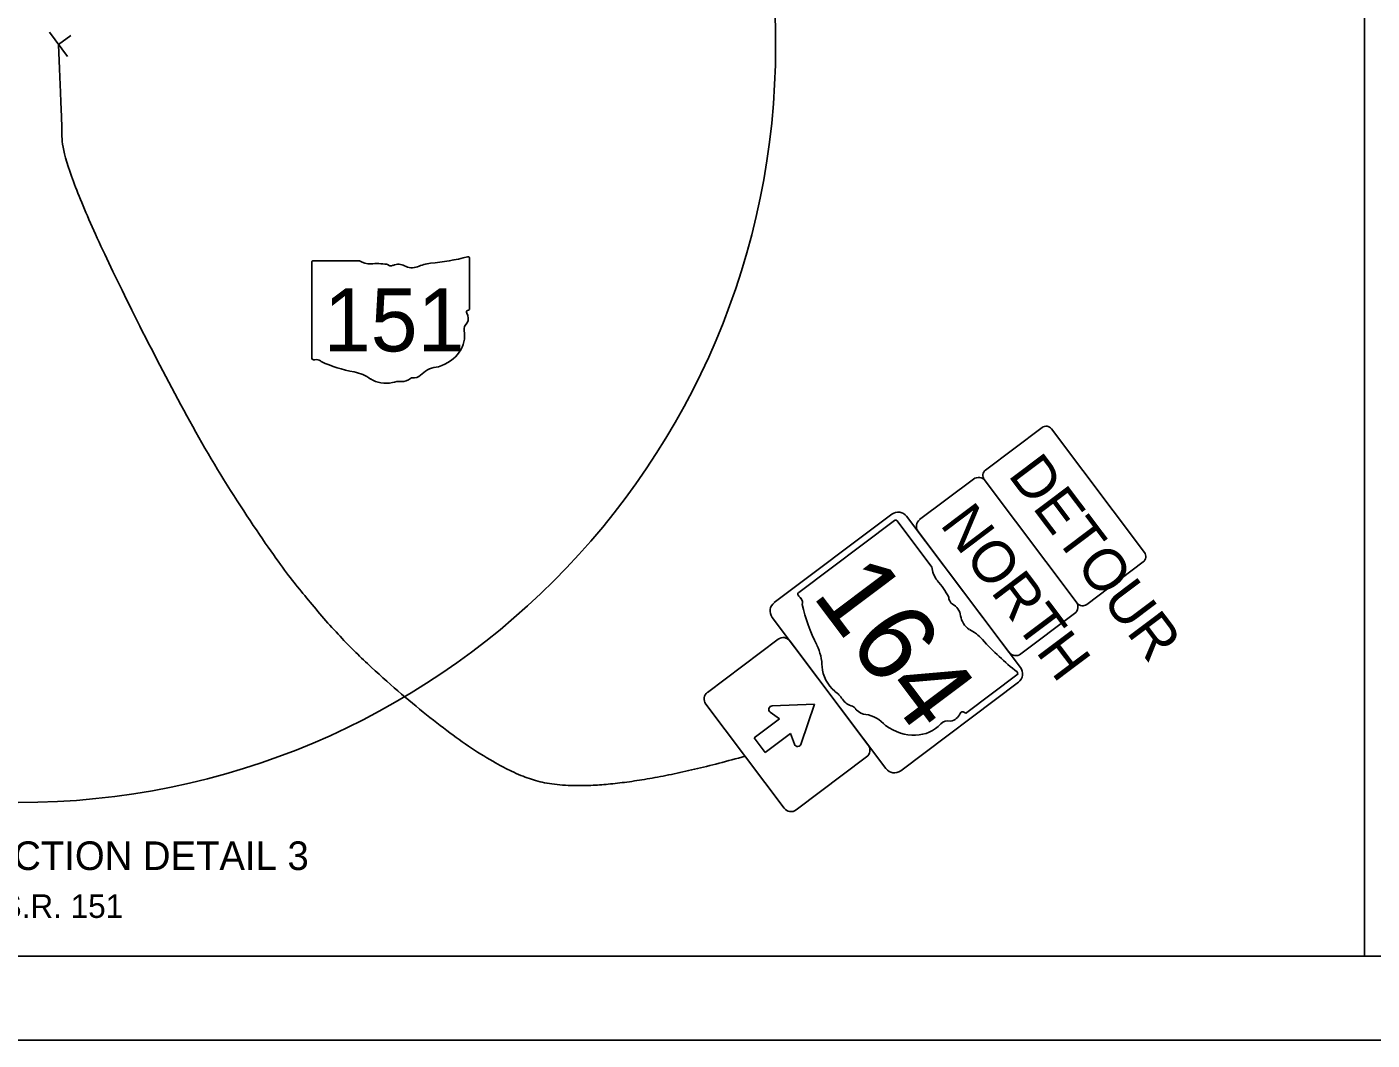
# Model space of a CAD drawing. Extents: x -740 to 1519, y 0 to 440.
# Drawn here: x 191 to 350.9, y 0 to 120.5 of the extents above; entities that cross this region are included whole.
import ezdxf

# ---------------------------------------------------------------- set-up
doc = ezdxf.new("R2010")
doc.units = 0
for name, color, linetype in [('GM_X_County_Road_Text', 7, 'Continuous'), ('GM_X_Minor_River', 7, 'Continuous'), ('GM_X_Section', 7, 'Continuous'), ('SH_Border', 7, 'Continuous'), ('SH_Cut_Line', 7, 'Continuous'), ('SH_Data', 7, 'Continuous')]:
    doc.layers.add(name, color=color, linetype=linetype)

msp = doc.modelspace()

# ---------------------------------------------------------------- linework, layer by layer
at = {"layer": 'GM_X_County_Road_Text'}
for p, q in [((243.63, 87.01), (243.63, 92.96)), ((224.88, 92.48), (224.88, 81.1)), ((230.55, 92.68), (225.06, 92.68)), ((243.63, 87.01), (243.63, 87.01))]:
    msp.add_line(p, q, dxfattribs=at)
for centre, major_axis, start_param, end_param in [((236.95, 108.2), (19.88, 0), 4.814394, 5.042369), ((243.42, 92.99), (0.209, 0), 6.141152, 7.989035), ((225.09, 92.51), (0.217, 0), 1.712693, 3.28349), ((231.86, 94), (2.11, 0), 4.042523, 4.731795), ((232.56, 86.29), (7.56, 0), 1.404758, 1.657858), ((234.28, 92.57), (0.608, 0), 3.836095, 5.185415), ((235.17, 91.25), (1.26, 0), 0.950623, 2.079405), ((236.8, 93.06), (1.52, 0), 4.081561, 5.145723), ((239.49, 89.2), (4, 0), 1.699011, 2.107814), ((243.58, 86.57), (0.323, 0), 1.883978, 3.671073), ((241.53, 85.82), (1.94, 0), 5.934695, 6.695948), ((243.41, 86.98), (0.223, 0), 5.05454, 6.418171), ((244.38, 84.51), (1.41, 0), 2.387724, 3.262537), ((238.06, 83.76), (4.97, 0), 5.101752, 6.440018), ((225.1, 81.07), (0.219, 0), 3.00124, 4.508301), ((225.13, 82.24), (1.67, 0), 4.665946, 4.897461), ((225.47, 80.44), (0.603, 0), 0.519207, 1.627899), ((233.08, 90.67), (14.36, 0), 4.195997, 4.488961), ((240.16, 77.9), (2.72, 0), 1.647645, 2.488434), ((228.8, 75.98), (4.49, 0), 0.823519, 1.323587), ((233.66, 80.39), (2.85, 0), 4.026481, 4.996735), ((235.52, 79.53), (1.52, 0), 4.691044, 5.507374), ((236.89, 78.43), (0.428, 0), 1.147584, 2.315152), ((236.71, 80), (1.61, 0), 4.937069, 5.64225), ((235.31, 76.45), (2.34, 0), 1.495662, 1.94098)]:
    msp.add_ellipse(centre, major_axis=major_axis, ratio=0.8, start_param=start_param, end_param=end_param, dxfattribs=at)
at = {"layer": 'GM_X_Minor_River'}
for p, q in [((195.82, 116.95), (193.71, 119.87)), ((194.76, 118.41), (196.22, 119.47)), ((297.12, 61.9), (303.52, 66.71)), ((304.92, 66.51), (315.74, 52.13)), ((294.12, 61.78), (282.75, 53.23)), ((298.58, 56.26), (294.45, 61.75)), ((307.75, 46.11), (296.93, 60.5)), ((315.54, 50.73), (309.15, 45.92)), ((271.91, 41.35), (280.3, 47.67)), ((281.7, 47.47), (291.02, 35.09)), ((302.74, 38.94), (308.69, 43.42)), ((281.03, 27.57), (271.71, 39.95)), ((280.46, 38.21), (279.37, 38.99)), ((279.6, 39.75), (284.61, 39.96)), ((284.61, 39.96), (283.03, 35.28)), ((302.74, 38.94), (302.74, 38.94)), ((277.46, 35.95), (280.46, 38.21)), ((278.78, 34.2), (277.46, 35.95)), ((281.77, 36.46), (278.78, 34.2)), ((282.23, 35.19), (281.77, 36.46)), ((290.82, 33.69), (282.43, 27.37))]:
    msp.add_line(p, q, dxfattribs=at)
for points in [[(311.67, 72.84), (304.96, 67.79)], [(323.85, 57.98), (312.79, 72.68)], [(304.8, 66.67), (315.86, 51.97)], [(279.84, 52.02), (293.82, 62.54)], [(295.57, 62.29), (309.1, 44.32)], [(316.98, 51.81), (323.69, 56.86)], [(293.12, 32.29), (279.59, 50.27)], [(308.86, 42.57), (294.88, 32.04)]]:
    msp.add_lwpolyline(points, dxfattribs=at)
for centre, radius, start, end in [((312.15, 72.2), 0.8, 36.9659, 126.9659), ((305.44, 67.15), 0.8, 126.9659, 216.9659), ((304.12, 65.91), 1, 36.9659, 126.9659), ((294.58, 61.54), 1.25, 36.9659, 126.9659), ((297.73, 61.1), 1, 126.9659, 216.9659), ((323.21, 57.5), 0.8, 306.9659, 36.9659), ((280.59, 51.02), 1.25, 126.9659, 216.9659), ((314.94, 51.53), 1, 306.9659, 36.9659), ((316.5, 52.45), 0.8, 216.9659, 306.9659), ((280.9, 46.87), 1, 36.9659, 126.9659), ((308.55, 46.72), 1, 216.9659, 306.9659), ((308.11, 43.56), 1.25, 306.9659, 36.9659), ((272.51, 40.56), 1, 126.9659, 216.9659), ((279.61, 39.33), 0.417, 92.3771, 234.1705), ((282.62, 35.33), 0.417, 199.7613, 351.9754), ((290.22, 34.48), 1, 306.9659, 36.9659), ((294.12, 33.04), 1.25, 216.9659, 306.9659), ((281.83, 28.17), 1, 216.9659, 306.9659)]:
    msp.add_arc(centre, radius, start, end, dxfattribs=at)
for centre, major_axis, start_param, end_param in [((294.3, 61.59), (0.163, -0.217), 1.712693, 3.28349), ((300.88, 55.95), (1.58, -2.1), 4.042523, 4.731795), ((293.7, 49.45), (5.69, -7.55), 1.404758, 1.657858), ((282.88, 52.99), (0.165, -0.219), 3.00124, 4.508301), ((284.07, 53.83), (1.26, -1.67), 4.665946, 4.897461), ((282.54, 52.14), (0.453, -0.602), 0.519207, 1.627899), ((298.47, 52.23), (10.79, -14.34), 4.195997, 4.488961), ((301.26, 52.46), (0.457, -0.607), 3.836095, 5.185415), ((300.62, 50.58), (0.95, -1.26), 0.950623, 2.079405), ((303.65, 50.31), (1.14, -1.52), 4.081561, 5.145723), ((301.82, 44.73), (3.01, -4), 1.699011, 2.107814), ((280.59, 45.46), (3.38, -4.49), 0.823519, 1.323587), ((318.89, 61.54), (14.95, -19.86), 4.814394, 5.042369), ((288.64, 43.92), (2.14, -2.85), 4.026481, 4.996735), ((308.56, 43.64), (0.157, -0.208), 6.141152, 7.989035), ((285.94, 39.31), (1.76, -2.34), 1.495662, 1.94098), ((289.18, 41.42), (1.14, -1.52), 4.691044, 5.507374), ((289.11, 39.22), (0.321, -0.427), 1.147584, 2.315152), ((290.54, 40.58), (1.21, -1.6), 4.937069, 5.64225), ((291.04, 35.56), (2.05, -2.72), 1.647645, 2.488434), ((299.97, 40.15), (1.46, -1.94), 5.934695, 6.695948), ((302.27, 38.66), (0.243, -0.323), 1.883978, 3.671073), ((302.55, 39.15), (0.168, -0.223), 5.05454, 6.418171), ((295.31, 42.06), (3.74, -4.97), 5.101752, 6.440018), ((300.81, 36.32), (1.06, -1.41), 2.387724, 3.262537)]:
    msp.add_ellipse(centre, major_axis=major_axis, ratio=0.8, start_param=start_param, end_param=end_param, dxfattribs=at)
at = {"layer": 'GM_X_Section'}
msp.add_line((350, 10), (350, 430), dxfattribs=at)
at = {"layer": 'SH_Border'}
msp.add_lwpolyline([(30, 430), (670, 430), (670, 10), (30, 10)], close=True, dxfattribs=at)
at = {"layer": 'SH_Cut_Line'}
msp.add_lwpolyline([(0, 0), (680, 0), (680, 440), (0, 440)], close=True, dxfattribs=at)
at = {"layer": 'SH_Data'}
msp.add_circle((190, 118.25), 90, dxfattribs=at)
msp.add_open_spline([(276.37, 33.76), (258.17, 28.67), (243.98, 33.29), (219.56, 55.74), (195.37, 102.27), (195.05, 111.86), (194.76, 118.41)], degree=2, dxfattribs=at)

# ---------------------------------------------------------------- texts
at = {"layer": 'GM_X_County_Road_Text'}
msp.add_text('151', height=7.5, dxfattribs=at).set_placement((226.29, 81.9))
at = {"layer": 'GM_X_Minor_River'}
for s, height, p in [('DETOUR', 5, (307.54, 67.19)), ('NORTH', 5, (299.45, 61.31)), ('164', 9.375, (284.24, 52.91))]:
    msp.add_text(s, height=height, rotation=306.9659, dxfattribs=at).set_placement(p)
at = {"layer": 'GM_X_Section'}
for s, height, p in [('DETOUR INTERSECTION DETAIL 3', 3.4, (149.23, 20.23)), ('S.R. 646 & S.R. 151', 2.8, (168.74, 14.53))]:
    msp.add_text(s, height=height, dxfattribs=at).set_placement(p)

doc.saveas('drawing.dxf')
